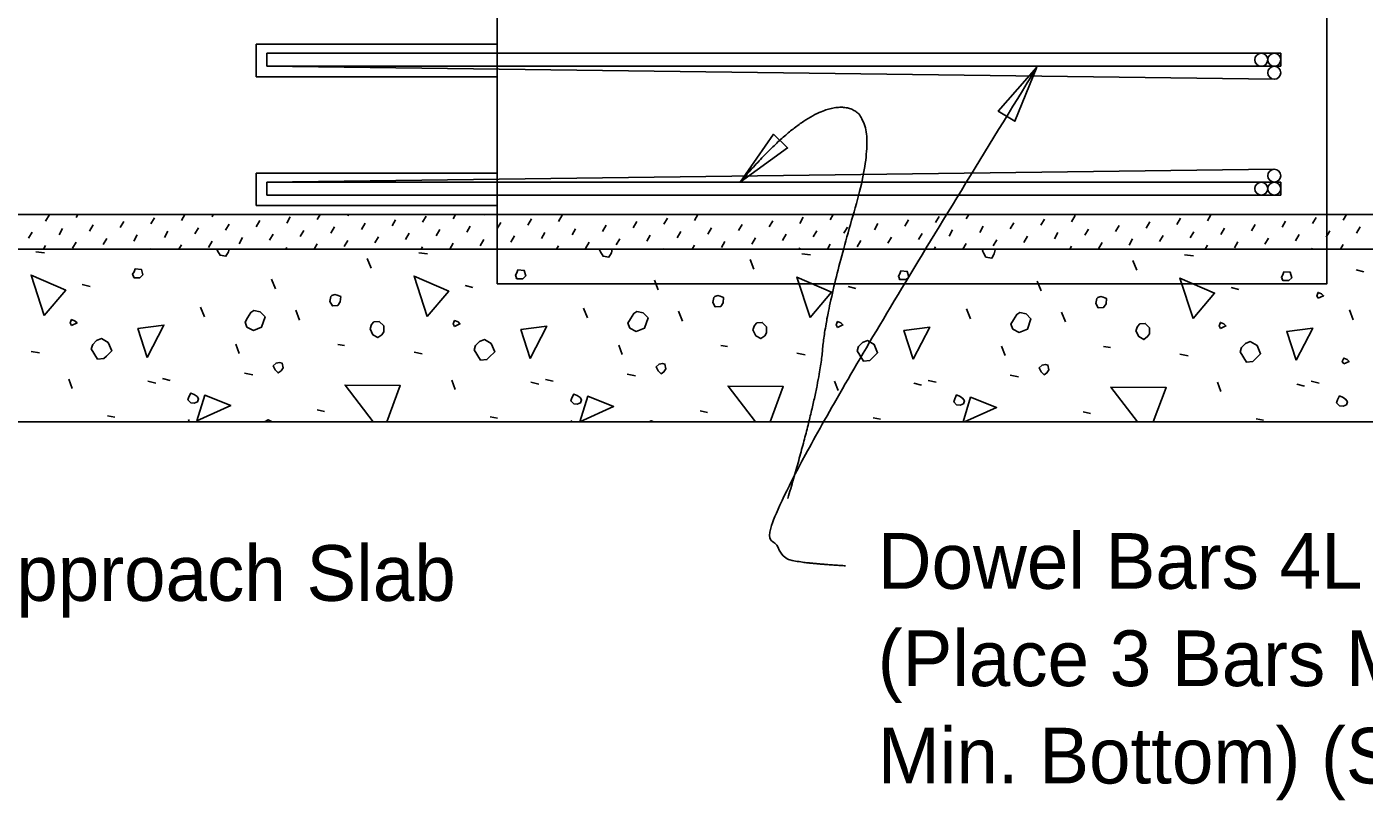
# Model space of a CAD drawing. Extents: x 21587 to 21656.3, y 56117.4 to 56157.3.
# Drawn here: x 21619.149 to 21623.985, y 56131.933 to 56134.73 of the extents above; entities that cross this region are included whole.
import ezdxf

# ---------------------------------------------------------------- set-up
doc = ezdxf.new("R2010")
doc.units = 0
for name, color, linetype in [('AdhocPoint_dp', 7, 'Continuous'), ('PlotBorder_dp', 7, 'Continuous'), ('SheetBorder_dp', 7, 'Continuous'), ('SheetLines_dp', 7, 'Continuous'), ('SubStrConc', 7, 'Continuous'), ('SubStrConc_h', 7, 'Continuous'), ('TextMisc', 7, 'Continuous')]:
    doc.layers.add(name, color=color, linetype=linetype)

msp = doc.modelspace()

# ---------------------------------------------------------------- linework, layer by layer
at = {"layer": 'AdhocPoint_dp'}
for p, q in [((21619.9783, 56134.6672), (21620.8503, 56134.6672)), ((21619.9783, 56134.6672), (21619.9783, 56134.5494)), ((21619.9783, 56134.5494), (21620.8503, 56134.5494)), ((21619.9783, 56134.2011), (21620.8503, 56134.2011)), ((21619.9783, 56134.2011), (21619.9783, 56134.0833)), ((21624.3563, 56134.0511), (21613.608, 56134.0511)), ((21619.9783, 56134.0833), (21620.8503, 56134.0833)), ((21613.608, 56133.926), (21624.3563, 56133.926)), ((21624.3563, 56133.301), (21618.8279, 56133.301))]:
    msp.add_line(p, q, dxfattribs=at)
at = {"layer": 'PlotBorder_dp'}
for points in [[(21622.8017, 56134.584), (21622.662, 56134.4255), (21622.722, 56134.3883)], [(21621.7288, 56134.1683), (21621.8998, 56134.2921), (21621.8495, 56134.3416)]]:
    msp.add_lwpolyline(points, close=True, dxfattribs=at)
for points in [[(21622.109, 56132.7809), (21621.9358, 56132.7915), (21621.8722, 56132.8163), (21621.805, 56132.9754), (21622.8016, 56134.584)], [(21621.9009, 56133.0246), (21622.0135, 56133.4067), (21622.0391, 56133.7156), (21622.2458, 56134.4216), (21621.9707, 56134.4548), (21621.7288, 56134.1683)]]:
    msp.add_open_spline(points, degree=2, dxfattribs=at)
at = {"layer": 'SheetLines_dp'}
for p, q in [((21623.6832, 56134.6343), (21620.0166, 56134.6343)), ((21620.0166, 56134.5874), (21620.0166, 56134.6343)), ((21623.6832, 56134.6343), (21623.6832, 56134.5874)), ((21623.6832, 56134.5874), (21620.0166, 56134.5874)), ((21623.6598, 56134.5406), (21620.0166, 56134.5874)), ((21623.6598, 56134.2152), (21620.0166, 56134.1683)), ((21623.6832, 56134.1683), (21620.0166, 56134.1683)), ((21620.0166, 56134.1214), (21620.0166, 56134.1683)), ((21623.6832, 56134.1683), (21623.6832, 56134.1214)), ((21623.6832, 56134.1214), (21620.0166, 56134.1214))]:
    msp.add_line(p, q, dxfattribs=at)
for centre in [(21623.6129, 56134.6109), (21623.6598, 56134.6109), (21623.6598, 56134.564), (21623.6598, 56134.1917), (21623.6129, 56134.1449), (21623.6598, 56134.1449)]:
    msp.add_circle(centre, 0.0234, dxfattribs=at)
at = {"layer": 'SubStrConc'}
for p, q in [((21620.8499, 56134.0509), (21620.8499, 56134.8009)), ((21623.8499, 56134.8009), (21623.8499, 56134.0509))]:
    msp.add_line(p, q, dxfattribs=at)
at = {"layer": 'SubStrConc_h'}
msp.add_lwpolyline([(21623.8499, 56134.0509), (21623.8499, 56133.8009), (21620.8499, 56133.8009), (21620.8499, 56134.0509)], dxfattribs=at)
at = {"layer": 'TextMisc'}
for p, q in [((21619.2168, 56134.0271), (21619.2298, 56134.0495)), ((21619.3275, 56134.04), (21619.3339, 56134.0511)), ((21619.7082, 56134.0301), (21619.7204, 56134.0511)), ((21619.8188, 56134.0431), (21619.8235, 56134.0511)), ((21620.1996, 56134.0331), (21620.21, 56134.0511)), ((21620.3102, 56134.0461), (21620.3131, 56134.0511)), ((21620.5803, 56134.0232), (21620.5933, 56134.0456)), ((21620.6909, 56134.0361), (21620.6996, 56134.0511)), ((21620.8016, 56134.0491), (21620.8027, 56134.0511)), ((21621.0717, 56134.0262), (21621.0846, 56134.0486)), ((21621.563, 56134.0292), (21621.5757, 56134.0511)), ((21622.0544, 56134.0322), (21622.0653, 56134.0511)), ((21622.4351, 56134.0223), (21622.4481, 56134.0447)), ((21622.5458, 56134.0353), (21622.5549, 56134.0511)), ((21622.9265, 56134.0253), (21622.9395, 56134.0477)), ((21623.4179, 56134.0283), (21623.4308, 56134.0507)), ((21623.9092, 56134.0314), (21623.9206, 56134.0511)), ((21619.2657, 56133.9782), (21619.2786, 56134.0006)), ((21619.3763, 56133.9912), (21619.3893, 56134.0136)), ((21619.4869, 56134.0042), (21619.4999, 56134.0266)), ((21619.5976, 56134.0171), (21619.6105, 56134.0395)), ((21619.757, 56133.9813), (21619.77, 56134.0037)), ((21619.8677, 56133.9942), (21619.8806, 56134.0166)), ((21619.9783, 56134.0072), (21619.9913, 56134.0296)), ((21620.0889, 56134.0202), (21620.1019, 56134.0426)), ((21620.2484, 56133.9843), (21620.2614, 56134.0067)), ((21620.359, 56133.9973), (21620.372, 56134.0196)), ((21620.4697, 56134.0102), (21620.4826, 56134.0326)), ((21620.6291, 56133.9743), (21620.6421, 56133.9967)), ((21620.7398, 56133.9873), (21620.7527, 56134.0097)), ((21620.8504, 56134.0003), (21620.8634, 56134.0227)), ((21620.961, 56134.0132), (21620.974, 56134.0356)), ((21621.1205, 56133.9774), (21621.1335, 56133.9998)), ((21621.2311, 56133.9903), (21621.2441, 56134.0127)), ((21621.3418, 56134.0033), (21621.3547, 56134.0257)), ((21621.4524, 56134.0163), (21621.4654, 56134.0386)), ((21621.6119, 56133.9804), (21621.6248, 56134.0028)), ((21621.7225, 56133.9933), (21621.7355, 56134.0157)), ((21621.8331, 56134.0063), (21621.8461, 56134.0287)), ((21621.9438, 56134.0193), (21621.9567, 56134.0417)), ((21622.1032, 56133.9834), (21622.1162, 56134.0058)), ((21622.2139, 56133.9964), (21622.2268, 56134.0188)), ((21622.3245, 56134.0093), (21622.3375, 56134.0317)), ((21622.484, 56133.9735), (21622.4969, 56133.9959)), ((21622.5946, 56133.9864), (21622.6076, 56134.0088)), ((21622.7052, 56133.9994), (21622.7182, 56134.0218)), ((21622.8159, 56134.0124), (21622.8288, 56134.0347)), ((21622.9753, 56133.9765), (21622.9883, 56133.9989)), ((21623.086, 56133.9894), (21623.0989, 56134.0118)), ((21623.1966, 56134.0024), (21623.2096, 56134.0248)), ((21623.3072, 56134.0154), (21623.3202, 56134.0378)), ((21623.4667, 56133.9795), (21623.4797, 56134.0019)), ((21623.5773, 56133.9925), (21623.5903, 56134.0149)), ((21623.688, 56134.0054), (21623.7009, 56134.0278)), ((21623.7986, 56134.0184), (21623.8116, 56134.0408)), ((21623.9571, 56133.9838), (21623.97, 56134.0062)), ((21619.155, 56133.9653), (21619.168, 56133.9877)), ((21619.3145, 56133.9294), (21619.3275, 56133.9518)), ((21619.4251, 56133.9424), (21619.4381, 56133.9648)), ((21619.5358, 56133.9553), (21619.5487, 56133.9777)), ((21619.6464, 56133.9683), (21619.6594, 56133.9907)), ((21619.8059, 56133.9324), (21619.8188, 56133.9548)), ((21619.9165, 56133.9454), (21619.9295, 56133.9678)), ((21620.0271, 56133.9584), (21620.0401, 56133.9808)), ((21620.1378, 56133.9713), (21620.1507, 56133.9937)), ((21620.2972, 56133.9355), (21620.3102, 56133.9578)), ((21620.4079, 56133.9484), (21620.4208, 56133.9708)), ((21620.5185, 56133.9614), (21620.5315, 56133.9838)), ((21620.6783, 56133.926), (21620.6909, 56133.9479)), ((21620.7886, 56133.9385), (21620.8016, 56133.9609)), ((21620.8992, 56133.9514), (21620.9122, 56133.9738)), ((21621.0099, 56133.9644), (21621.0228, 56133.9868)), ((21621.1693, 56133.9285), (21621.1823, 56133.9509)), ((21621.28, 56133.9415), (21621.2929, 56133.9639)), ((21621.3906, 56133.9545), (21621.4036, 56133.9768)), ((21621.5012, 56133.9674), (21621.5142, 56133.9898)), ((21621.6607, 56133.9315), (21621.6737, 56133.9539)), ((21621.7713, 56133.9445), (21621.7843, 56133.9669)), ((21621.882, 56133.9575), (21621.8949, 56133.9799)), ((21621.9926, 56133.9704), (21622.0056, 56133.9928)), ((21622.1521, 56133.9346), (21622.165, 56133.957)), ((21622.2627, 56133.9475), (21622.2757, 56133.9699)), ((21622.3733, 56133.9605), (21622.3863, 56133.9829)), ((21622.6434, 56133.9376), (21622.6564, 56133.96)), ((21622.7541, 56133.9506), (21622.767, 56133.9729)), ((21622.8647, 56133.9635), (21622.8777, 56133.9859)), ((21623.0242, 56133.9276), (21623.0371, 56133.95)), ((21623.1348, 56133.9406), (21623.1478, 56133.963)), ((21623.2454, 56133.9536), (21623.2584, 56133.976)), ((21623.3561, 56133.9665), (21623.369, 56133.9889)), ((21623.5155, 56133.9307), (21623.5285, 56133.9531)), ((21623.6262, 56133.9436), (21623.6391, 56133.966)), ((21623.7368, 56133.9566), (21623.7498, 56133.979)), ((21623.8474, 56133.9696), (21623.8604, 56133.9919)), ((21619.1816, 56133.9165), (21619.2134, 56133.913)), ((21619.2094, 56133.926), (21619.2168, 56133.9388)), ((21619.5959, 56133.926), (21619.5976, 56133.9289)), ((21619.699, 56133.926), (21619.7082, 56133.9419)), ((21620.0855, 56133.926), (21620.0889, 56133.9319)), ((21620.1886, 56133.926), (21620.1996, 56133.9449)), ((21620.5663, 56133.913), (21620.5981, 56133.9094)), ((21620.5751, 56133.926), (21620.5803, 56133.9349)), ((21621.0648, 56133.926), (21621.0717, 56133.938)), ((21621.4512, 56133.926), (21621.4524, 56133.928)), ((21621.5544, 56133.926), (21621.563, 56133.941)), ((21621.9409, 56133.926), (21621.9438, 56133.931)), ((21621.951, 56133.9094), (21621.9828, 56133.9059)), ((21622.044, 56133.926), (21622.0544, 56133.944)), ((21622.4305, 56133.926), (21622.4351, 56133.9341)), ((21622.5336, 56133.926), (21622.5458, 56133.947)), ((21622.9201, 56133.926), (21622.9265, 56133.9371)), ((21623.3066, 56133.926), (21623.3072, 56133.9271)), ((21623.3356, 56133.9059), (21623.3675, 56133.9024)), ((21623.4097, 56133.926), (21623.4179, 56133.9401)), ((21623.7962, 56133.926), (21623.7986, 56133.9302)), ((21623.8993, 56133.926), (21623.9092, 56133.9431)), ((21620.3937, 56133.857), (21620.3795, 56133.8924)), ((21621.7784, 56133.8535), (21621.7642, 56133.8889)), ((21623.163, 56133.85), (21623.1489, 56133.8853)), ((21623.9556, 56133.8507), (21623.9839, 56133.8437)), ((21620.0478, 56133.7822), (21620.0337, 56133.8175)), ((21621.4325, 56133.7786), (21621.4184, 56133.814)), ((21622.8172, 56133.7751), (21622.803, 56133.8104)), ((21619.3496, 56133.7981), (21619.3778, 56133.791)), ((21620.7342, 56133.7945), (21620.7625, 56133.7875)), ((21622.1189, 56133.791), (21622.1472, 56133.7839)), ((21623.5036, 56133.7875), (21623.5319, 56133.7804)), ((21619.7915, 56133.6814), (21619.7774, 56133.7168)), ((21621.1762, 56133.6779), (21621.162, 56133.7132)), ((21622.5609, 56133.6743), (21622.5467, 56133.7097)), ((21623.9455, 56133.6708), (21623.9314, 56133.7062)), ((21620.1356, 56133.6697), (21620.1214, 56133.705)), ((21621.5203, 56133.6661), (21621.5061, 56133.7015)), ((21622.9049, 56133.6626), (21622.8908, 56133.6979)), ((21619.917, 56133.5488), (21619.9046, 56133.5824)), ((21620.2735, 56133.5813), (21620.2982, 56133.5777)), ((21621.3017, 56133.5453), (21621.2893, 56133.5789)), ((21621.6581, 56133.5777), (21621.6829, 56133.5742)), ((21622.6864, 56133.5417), (21622.674, 56133.5753)), ((21623.0428, 56133.5742), (21623.0676, 56133.5707)), ((21619.1646, 56133.5565), (21619.1946, 56133.5512)), ((21620.5492, 56133.553), (21620.5793, 56133.5477)), ((21621.9339, 56133.5494), (21621.964, 56133.5441)), ((21623.3186, 56133.5459), (21623.3486, 56133.5406)), ((21619.9358, 56133.477), (21619.9659, 56133.4717)), ((21621.3205, 56133.4734), (21621.3506, 56133.4681)), ((21622.7052, 56133.4699), (21622.7352, 56133.4646)), ((21619.3131, 56133.4222), (21619.3007, 56133.4558)), ((21619.5871, 56133.4487), (21619.6153, 56133.4416)), ((21619.6395, 56133.4587), (21619.6678, 56133.4516)), ((21620.6977, 56133.4186), (21620.6854, 56133.4522)), ((21620.9717, 56133.4451), (21621, 56133.4381)), ((21621.0241, 56133.4551), (21621.0524, 56133.4481)), ((21622.0824, 56133.4151), (21622.07, 56133.4487)), ((21622.3564, 56133.4416), (21622.3847, 56133.4345)), ((21622.4088, 56133.4516), (21622.4371, 56133.4445)), ((21623.4671, 56133.4116), (21623.4547, 56133.4451)), ((21623.7411, 56133.4381), (21623.7694, 56133.431)), ((21623.7935, 56133.4481), (21623.8218, 56133.441)), ((21619.4403, 56133.3232), (21619.4669, 56133.3179)), ((21620.1992, 56133.3444), (21620.2257, 56133.3391)), ((21620.825, 56133.3196), (21620.8515, 56133.3143)), ((21621.5839, 56133.3408), (21621.6104, 56133.3355)), ((21622.9686, 56133.3373), (21622.9951, 56133.332)), ((21619.7364, 56133.301), (21619.7332, 56133.3097)), ((21621.1197, 56133.301), (21621.1178, 56133.3061)), ((21622.2097, 56133.3161), (21622.2362, 56133.3108)), ((21622.5031, 56133.301), (21622.5025, 56133.3026)), ((21623.5944, 56133.3126), (21623.6209, 56133.3073))]:
    msp.add_line(p, q, dxfattribs=at)
for points in [[(21619.8362, 56133.926), (21619.8392, 56133.9201)], [(21619.8392, 56133.9201), (21619.8481, 56133.9041), (21619.8693, 56133.9006), (21619.8781, 56133.9165), (21619.8805, 56133.926)], [(21621.2212, 56133.926), (21621.2204, 56133.9236), (21621.2239, 56133.9165)], [(21621.2239, 56133.9165), (21621.2327, 56133.9006), (21621.254, 56133.8971), (21621.2628, 56133.913), (21621.2661, 56133.926)], [(21622.607, 56133.926), (21622.605, 56133.9201), (21622.6086, 56133.913)], [(21622.6086, 56133.913), (21622.6174, 56133.8971), (21622.6386, 56133.8935), (21622.6475, 56133.9094), (21622.651, 56133.9236), (21622.6486, 56133.926)], [(21619.5369, 56133.8228), (21619.5582, 56133.8228), (21619.5688, 56133.8334), (21619.5635, 56133.8529), (21619.5405, 56133.8546), (21619.5369, 56133.844), (21619.5316, 56133.8352), (21619.5369, 56133.8228), (21619.5334, 56133.8264)], [(21620.9216, 56133.8193), (21620.9428, 56133.8193), (21620.9534, 56133.8299), (21620.9481, 56133.8493), (21620.9252, 56133.8511), (21620.9216, 56133.8405), (21620.9163, 56133.8317), (21620.9216, 56133.8193), (21620.9181, 56133.8228)], [(21619.2123, 56133.6856), (21619.1646, 56133.8323), (21619.2901, 56133.7775), (21619.2123, 56133.6856)], [(21620.597, 56133.682), (21620.5492, 56133.8288), (21620.6748, 56133.774), (21620.597, 56133.682)], [(21621.9816, 56133.6785), (21621.9339, 56133.8252), (21622.0594, 56133.7704), (21621.9816, 56133.6785)], [(21622.3063, 56133.8158), (21622.3275, 56133.8158), (21622.3381, 56133.8264), (21622.3328, 56133.8458), (21622.3098, 56133.8476), (21622.3063, 56133.837), (21622.301, 56133.8281), (21622.3063, 56133.8158), (21622.3028, 56133.8193)], [(21623.3663, 56133.675), (21623.3186, 56133.8217), (21623.4441, 56133.7669), (21623.3663, 56133.675)], [(21623.691, 56133.8122), (21623.7122, 56133.8122), (21623.7228, 56133.8228), (21623.7175, 56133.8423), (21623.6945, 56133.844), (21623.691, 56133.8334), (21623.6857, 56133.8246), (21623.691, 56133.8122), (21623.6874, 56133.8158)], [(21620.2452, 56133.7368), (21620.254, 56133.7209), (21620.2735, 56133.7227), (21620.2823, 56133.7351), (21620.2841, 56133.7545), (21620.2717, 56133.7598), (21620.2629, 56133.7616), (21620.2523, 56133.758), (21620.2487, 56133.7545), (21620.2452, 56133.7368)], [(21621.6299, 56133.7333), (21621.6387, 56133.7174), (21621.6581, 56133.7192), (21621.667, 56133.7315), (21621.6688, 56133.751), (21621.6564, 56133.7563), (21621.6475, 56133.758), (21621.6369, 56133.7545), (21621.6334, 56133.751), (21621.6299, 56133.7333)], [(21623.0145, 56133.7298), (21623.0234, 56133.7138), (21623.0428, 56133.7156), (21623.0517, 56133.728), (21623.0534, 56133.7474), (21623.0411, 56133.7527), (21623.0322, 56133.7545), (21623.0216, 56133.751), (21623.0181, 56133.7474), (21623.0145, 56133.7298)], [(21623.8185, 56133.7486), (21623.8379, 56133.7574), (21623.8308, 56133.7645), (21623.8185, 56133.7698), (21623.8132, 56133.7574), (21623.8185, 56133.7486)], [(21619.3113, 56133.6502), (21619.3307, 56133.659), (21619.3237, 56133.6661), (21619.3113, 56133.6714), (21619.306, 56133.659), (21619.3113, 56133.6502)], [(21619.9453, 56133.6443), (21619.9683, 56133.6319), (21619.9983, 56133.6443), (21620.0107, 56133.6814), (21619.993, 56133.6991), (21619.97, 56133.7044), (21619.9594, 56133.6973), (21619.9471, 56133.6779), (21619.9382, 56133.662), (21619.9453, 56133.6443)], [(21620.3901, 56133.6378), (21620.4008, 56133.6166), (21620.4184, 56133.606), (21620.4326, 56133.6166), (21620.4396, 56133.6272), (21620.4396, 56133.6484), (21620.4237, 56133.6644), (21620.4043, 56133.6626), (21620.3954, 56133.6537), (21620.3901, 56133.6378)], [(21620.696, 56133.6467), (21620.7154, 56133.6555), (21620.7083, 56133.6626), (21620.696, 56133.6679), (21620.6907, 56133.6555), (21620.696, 56133.6467)], [(21621.33, 56133.6407), (21621.353, 56133.6284), (21621.383, 56133.6407), (21621.3954, 56133.6779), (21621.3777, 56133.6955), (21621.3547, 56133.7008), (21621.3441, 56133.6938), (21621.3317, 56133.6743), (21621.3229, 56133.6584), (21621.33, 56133.6407)], [(21621.7748, 56133.6343), (21621.7854, 56133.6131), (21621.8031, 56133.6025), (21621.8172, 56133.6131), (21621.8243, 56133.6237), (21621.8243, 56133.6449), (21621.8084, 56133.6608), (21621.789, 56133.659), (21621.7801, 56133.6502), (21621.7748, 56133.6343)], [(21622.0806, 56133.6431), (21622.1001, 56133.652), (21622.093, 56133.659), (21622.0806, 56133.6644), (21622.0753, 56133.652), (21622.0806, 56133.6431)], [(21622.7146, 56133.6372), (21622.7376, 56133.6248), (21622.7677, 56133.6372), (21622.7801, 56133.6743), (21622.7624, 56133.692), (21622.7394, 56133.6973), (21622.7288, 56133.6902), (21622.7164, 56133.6708), (21622.7076, 56133.6549), (21622.7146, 56133.6372)], [(21623.1595, 56133.6308), (21623.1701, 56133.6096), (21623.1878, 56133.5989), (21623.2019, 56133.6096), (21623.209, 56133.6202), (21623.209, 56133.6414), (21623.1931, 56133.6573), (21623.1736, 56133.6555), (21623.1648, 56133.6467), (21623.1595, 56133.6308)], [(21623.4653, 56133.6396), (21623.4848, 56133.6484), (21623.4777, 56133.6555), (21623.4653, 56133.6608), (21623.46, 56133.6484), (21623.4653, 56133.6396)], [(21619.5847, 56133.5347), (21619.5511, 56133.639), (21619.6448, 56133.6514), (21619.5847, 56133.5347)], [(21620.9693, 56133.5311), (21620.9358, 56133.6354), (21621.0294, 56133.6478), (21620.9693, 56133.5311)], [(21622.354, 56133.5276), (21622.3204, 56133.6319), (21622.4141, 56133.6443), (21622.354, 56133.5276)], [(21623.7387, 56133.5241), (21623.7051, 56133.6284), (21623.7988, 56133.6407), (21623.7387, 56133.5241)], [(21619.382, 56133.5654), (21619.405, 56133.5282), (21619.428, 56133.53), (21619.4368, 56133.5388), (21619.4562, 56133.5583), (21619.4439, 56133.5883), (21619.4191, 56133.6025), (21619.4014, 56133.5954), (21619.3873, 56133.5813), (21619.382, 56133.5654)], [(21620.7667, 56133.5618), (21620.7897, 56133.5247), (21620.8126, 56133.5265), (21620.8215, 56133.5353), (21620.8409, 56133.5547), (21620.8285, 56133.5848), (21620.8038, 56133.5989), (21620.7861, 56133.5919), (21620.772, 56133.5777), (21620.7667, 56133.5618)], [(21622.1514, 56133.5583), (21622.1743, 56133.5212), (21622.1973, 56133.5229), (21622.2062, 56133.5318), (21622.2256, 56133.5512), (21622.2132, 56133.5813), (21622.1885, 56133.5954), (21622.1708, 56133.5883), (21622.1567, 56133.5742), (21622.1514, 56133.5583)], [(21623.536, 56133.5547), (21623.559, 56133.5176), (21623.582, 56133.5194), (21623.5908, 56133.5282), (21623.6103, 56133.5477), (21623.5979, 56133.5777), (21623.5732, 56133.5919), (21623.5555, 56133.5848), (21623.5413, 56133.5707), (21623.536, 56133.5547)], [(21620.0472, 56133.4893), (21620.0578, 56133.4787), (21620.0684, 56133.4858), (21620.0755, 56133.4964), (21620.0719, 56133.5141), (21620.0631, 56133.5159), (21620.0507, 56133.5141), (21620.0401, 56133.5035), (21620.0472, 56133.4893)], [(21621.4319, 56133.4858), (21621.4425, 56133.4752), (21621.4531, 56133.4823), (21621.4602, 56133.4929), (21621.4566, 56133.5106), (21621.4478, 56133.5123), (21621.4354, 56133.5106), (21621.4248, 56133.4999), (21621.4319, 56133.4858)], [(21623.9109, 56133.5108), (21623.9303, 56133.5197), (21623.9232, 56133.5267), (21623.9109, 56133.5321), (21623.9056, 56133.5197), (21623.9109, 56133.5108)], [(21622.8166, 56133.4823), (21622.8272, 56133.4717), (21622.8378, 56133.4787), (21622.8448, 56133.4893), (21622.8413, 56133.507), (21622.8325, 56133.5088), (21622.8201, 56133.507), (21622.8095, 56133.4964), (21622.8166, 56133.4823)], [(21620.4015, 56133.301), (21620.3, 56133.4345), (21620.4997, 56133.4328), (21620.4505, 56133.301)], [(21621.7835, 56133.301), (21621.6847, 56133.431), (21621.8844, 56133.4292), (21621.8365, 56133.301)], [(21623.1655, 56133.301), (21623.0693, 56133.4275), (21623.2691, 56133.4257), (21623.2225, 56133.301)], [(21619.742, 56133.3703), (21619.7544, 56133.3685), (21619.7667, 56133.3738), (21619.7703, 56133.3844), (21619.765, 56133.3933), (21619.7544, 56133.4003), (21619.742, 56133.4056), (21619.7349, 56133.3915), (21619.7314, 56133.3809), (21619.742, 56133.3703)], [(21619.7644, 56133.3055), (21619.7926, 56133.3974), (21619.8863, 56133.3603), (21619.7644, 56133.3055)], [(21621.1267, 56133.3667), (21621.1391, 56133.365), (21621.1514, 56133.3703), (21621.155, 56133.3809), (21621.1497, 56133.3897), (21621.1391, 56133.3968), (21621.1267, 56133.4021), (21621.1196, 56133.388), (21621.1161, 56133.3773), (21621.1267, 56133.3667)], [(21621.149, 56133.302), (21621.1773, 56133.3939), (21621.271, 56133.3568), (21621.149, 56133.302)], [(21622.5114, 56133.3632), (21622.5237, 56133.3614), (21622.5361, 56133.3667), (21622.5396, 56133.3773), (21622.5343, 56133.3862), (21622.5237, 56133.3933), (21622.5114, 56133.3986), (21622.5043, 56133.3844), (21622.5007, 56133.3738), (21622.5114, 56133.3632)], [(21622.5345, 56133.301), (21622.562, 56133.3903), (21622.6557, 56133.3532), (21622.5394, 56133.301)], [(21623.896, 56133.3597), (21623.9084, 56133.3579), (21623.9208, 56133.3632), (21623.9243, 56133.3738), (21623.919, 56133.3827), (21623.9084, 56133.3897), (21623.896, 56133.395), (21623.889, 56133.3809), (21623.8854, 56133.3703), (21623.896, 56133.3597)], [(21620.0368, 56133.301), (21620.0366, 56133.302), (21620.0224, 56133.309), (21620.009, 56133.301)], [(21621.4161, 56133.301), (21621.4071, 56133.3055), (21621.3996, 56133.301)], [(21622.7937, 56133.301), (21622.7918, 56133.302), (21622.7902, 56133.301)]]:
    msp.add_lwpolyline(points, dxfattribs=at)

# ---------------------------------------------------------------- texts
at = {"layer": 'PlotBorder_dp'}
for s, p in [('Dowel Bars 4L (10" Embedment) ', (21622.226, 56132.6977)), ('(Place 3 Bars Min. Top and 1 Bar ', (21622.226, 56132.3457)), ('Min. Bottom) (See Note 2)', (21622.226, 56131.9937))]:
    msp.add_text(s, height=0.2016, dxfattribs=at).set_placement(p)
at = {"layer": 'SheetBorder_dp'}
msp.add_text('Existing Approach Slab', height=0.2016, dxfattribs=at).set_placement((21617.9127, 56132.654))

doc.saveas('drawing.dxf')
